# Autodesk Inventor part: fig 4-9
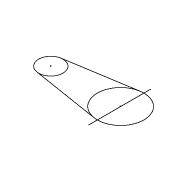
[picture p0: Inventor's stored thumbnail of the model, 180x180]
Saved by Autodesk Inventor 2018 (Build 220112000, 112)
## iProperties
Created: 2005-02
Part Number: fig 4-9
Document SubType Name: Modeling
Designer: CADCIM
Manufacturer: Standard
Standards Organization: Custom
Density: 1 g/cm^3
Material: Generic
Appearance: Default
Author: CADCIM
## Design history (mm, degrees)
sketch "Sketch1"
  geometry: L1 (-28.496, 15.735)-(10.446, 21.986); L2 (-28.503, 2.004)-(10.432, -4.291); L3 (12.58, 26.117)-(12.58, -9.642); A1 r 6.954 centre (-27.393, 8.869) between (-28.496, 15.735) and (-28.503, 2.004); A2 r 13.308 centre (12.555, 8.846) between (10.446, 21.986) and (10.432, -4.291)
  constraints: 6 end point, 4 point on circle, 4 tangent, 2 centre point, 1 vertical, 1 other
